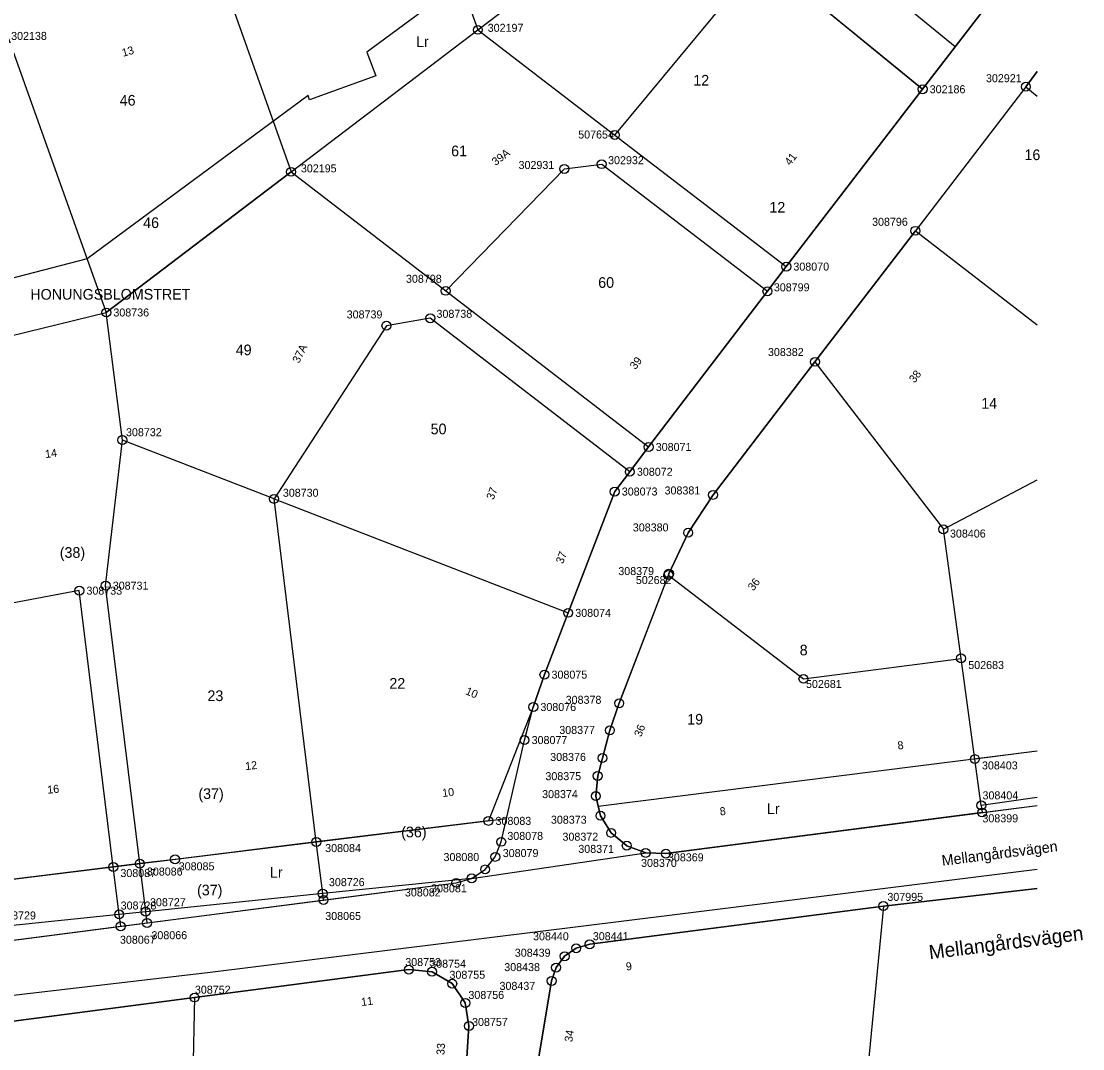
# Model space of a CAD drawing. Extents: x 141995 to 152570, y 6580184 to 6586000.
# Drawn here: x 142885.7 to 143005.1, y 6585147.6 to 6585263.2 of the extents above; entities that cross this region are included whole.
import ezdxf

# ---------------------------------------------------------------- set-up
doc = ezdxf.new("R2010")
doc.units = 0
for name, color, linetype in [('Level 10', 7, 'Continuous'), ('Level 34', 7, 'Continuous'), ('Level 42', 7, 'Continuous'), ('Level 43', 7, 'Continuous'), ('Level 48', 7, 'Continuous'), ('Level 5', 7, 'Continuous'), ('Level 50', 7, 'Continuous'), ('Level 51', 7, 'Continuous'), ('Level 52', 7, 'Continuous'), ('Level 53', 7, 'Continuous'), ('Level 54', 7, 'Continuous'), ('Level 55', 7, 'Continuous'), ('Level 59', 7, 'Continuous'), ('Level 6', 7, 'Continuous'), ('Level 60', 7, 'Continuous'), ('Level 7', 7, 'Continuous'), ('Level 9', 7, 'Continuous')]:
    doc.layers.add(name, color=color, linetype=linetype)

msp = doc.modelspace()

# ---------------------------------------------------------------- linework, layer by layer
at = {"layer": 'Level 10'}
for centre in [(142937.08, 6585262.24), (142987.1, 6585255.56), (142998.71, 6585255.85), (142952.49, 6585250.41), (142946.81, 6585246.6), (142951.01, 6585247.13), (142916.07, 6585246.27), (142986.29, 6585239.64), (142971.77, 6585235.61), (142933.47, 6585232.88), (142969.65, 6585232.83), (142895.29, 6585230.45), (142926.8, 6585228.96), (142931.73, 6585229.8), (142975, 6585224.9), (142897.1, 6585216.1), (142956.29, 6585215.32), (142954.17, 6585212.53), (142952.47, 6585210.3), (142963.53, 6585209.93), (142914.16, 6585209.48), (142989.44, 6585206.06), (142960.73, 6585205.68), (142958.51, 6585200.92), (142958.57, 6585201.07), (142892.26, 6585199.16), (142895.22, 6585199.72), (142947.24, 6585196.66), (142991.43, 6585191.54), (142944.57, 6585189.71), (142973.7, 6585189.24), (142943.32, 6585186.07), (142952.98, 6585186.49), (142951.93, 6585183.45), (142942.33, 6585182.35), (142951.1, 6585180.33), (142992.98, 6585180.21), (142950.56, 6585178.32), (142950.35, 6585176.05), (142993.7, 6585175), (142950.87, 6585173.84), (142993.8, 6585174.2), (142938.27, 6585173.26), (142952.07, 6585171.91), (142918.91, 6585170.89), (142939.71, 6585170.9), (142953.83, 6585170.47), (142939.04, 6585169.21), (142955.96, 6585169.66), (142958.23, 6585169.58), (142896.08, 6585168.08), (142899.06, 6585168.45), (142903.03, 6585168.93), (142937.9, 6585167.8), (142936.38, 6585166.79), (142934.64, 6585166.29), (142919.63, 6585165.08), (142919.72, 6585164.36), (142899.73, 6585163.04), (142982.69, 6585163.68), (142896.74, 6585162.74), (142896.91, 6585161.4), (142899.88, 6585161.78), (142948.14, 6585158.93), (142949.66, 6585159.38), (142946.84, 6585158.03), (142929.32, 6585156.53), (142931.93, 6585156.29), (142945.88, 6585156.76), (142934.2, 6585154.95), (142945.38, 6585155.26), (142905.22, 6585153.39), (142935.67, 6585152.78), (142936.08, 6585150.19)]:
    msp.add_circle(centre, 0.5, dxfattribs=at)
at = {"layer": 'Level 34'}
for points in [[(142868.26, 6585230.02), (142870.29, 6585224.35), (142895.29, 6585230.45), (142916.07, 6585246.27), (142937.08, 6585262.24), (142958.78, 6585278.74), (142987.1, 6585255.56), (142990.76, 6585260.32), (142959.77, 6585285.68), (142924.61, 6585259.72), (142925.59, 6585257.07), (142918.16, 6585254.37), (142918, 6585254.84), (142893.13, 6585236.49)], [(142788.7, 6585154.87), (142790.99, 6585151.54), (142793.5, 6585150.06), (142796.39, 6585149.74), (142819.3, 6585151.94), (142847.82, 6585155.05), (142934.64, 6585166.29), (142936.38, 6585166.79), (142937.9, 6585167.8), (142939.04, 6585169.21), (142939.71, 6585170.9), (142940.31, 6585173.51)]]:
    msp.add_lwpolyline(points, close=True, dxfattribs=at)
msp.add_lwpolyline([(143000, 6585181.09), (142950.62, 6585174.88), (142950.87, 6585173.84), (142952.07, 6585171.91), (142953.83, 6585170.47), (142955.96, 6585169.66), (142958.23, 6585169.58), (143000, 6585175.01)], dxfattribs=at)
at = {"layer": 'Level 5'}
for points in [[(143000, 6585272.35), (142987.1, 6585255.56)], [(142998.71, 6585255.85), (143000, 6585257.54)], [(142987.1, 6585255.56), (142971.77, 6585235.61)], [(142998.71, 6585255.85), (142986.29, 6585239.64)], [(142975, 6585224.9), (142986.29, 6585239.64)], [(142971.77, 6585235.61), (142969.65, 6585232.83)], [(142969.65, 6585232.83), (142956.29, 6585215.32)], [(142963.53, 6585209.93), (142975, 6585224.9)], [(142956.29, 6585215.32), (142954.17, 6585212.53)], [(142954.17, 6585212.53), (142952.47, 6585210.3)], [(142952.47, 6585210.3), (142947.24, 6585196.66)], [(142960.73, 6585205.68), (142963.53, 6585209.93)], [(142958.57, 6585201.07), (142960.73, 6585205.68)], [(142952.98, 6585186.49), (142958.51, 6585200.92)], [(142958.51, 6585200.92), (142958.57, 6585201.07)], [(142947.24, 6585196.66), (142944.57, 6585189.71)], [(142944.57, 6585189.71), (142943.32, 6585186.07)], [(142951.93, 6585183.45), (142952.98, 6585186.49)], [(142943.32, 6585186.07), (142938.27, 6585173.26)], [(142951.1, 6585180.33), (142951.93, 6585183.45)], [(142950.56, 6585178.32), (142951.1, 6585180.33)], [(143000, 6585181.09), (142992.98, 6585180.21)], [(142993.7, 6585175), (142992.98, 6585180.21)], [(142950.35, 6585176.05), (142950.56, 6585178.32)], [(142950.87, 6585173.84), (142950.35, 6585176.05)], [(142993.7, 6585175), (142993.8, 6585174.2)], [(142938.27, 6585173.26), (142918.91, 6585170.89)], [(142952.07, 6585171.91), (142950.87, 6585173.84)], [(142993.8, 6585174.2), (142958.23, 6585169.58)], [(142953.83, 6585170.47), (142952.07, 6585171.91)], [(142918.91, 6585170.89), (142903.03, 6585168.93)], [(142955.96, 6585169.66), (142953.83, 6585170.47)], [(142958.23, 6585169.58), (142955.96, 6585169.66)], [(142899.06, 6585168.45), (142896.08, 6585168.08)], [(142903.03, 6585168.93), (142899.06, 6585168.45)], [(142896.08, 6585168.08), (142877.39, 6585165.78)], [(142982.69, 6585163.68), (143000, 6585165.66)], [(142949.66, 6585159.38), (142982.69, 6585163.68)], [(142946.84, 6585158.03), (142948.14, 6585158.93)], [(142948.14, 6585158.93), (142949.66, 6585159.38)], [(142945.88, 6585156.76), (142946.84, 6585158.03)], [(142905.22, 6585153.39), (142929.32, 6585156.53)], [(142929.32, 6585156.53), (142931.93, 6585156.29)], [(142945.38, 6585155.26), (142945.88, 6585156.76)], [(142931.93, 6585156.29), (142934.2, 6585154.95)], [(142942.47, 6585137.91), (142945.38, 6585155.26)], [(142934.2, 6585154.95), (142935.67, 6585152.78)], [(142877.35, 6585149.77), (142905.22, 6585153.39)], [(142935.67, 6585152.78), (142936.08, 6585150.19)], [(142936.08, 6585150.19), (142934.45, 6585124.56)]]:
    msp.add_lwpolyline(points, dxfattribs=at)
at = {"layer": 'Level 6'}
for points in [[(142874.1, 6585158.44), (142896.91, 6585161.4), (142899.88, 6585161.78), (142919.72, 6585164.36), (142934.64, 6585166.29), (142936.38, 6585166.79), (142937.9, 6585167.8), (142939.04, 6585169.21), (142939.71, 6585170.9), (142942.33, 6585182.35), (142943.32, 6585186.07), (142944.57, 6585189.71), (142947.24, 6585196.66), (142952.47, 6585210.3), (142954.17, 6585212.53), (142956.29, 6585215.32), (142969.65, 6585232.83), (142971.77, 6585235.61), (142987.1, 6585255.56), (143000, 6585272.35)], [(143000, 6585257.54), (142998.71, 6585255.85), (142986.29, 6585239.64), (142975, 6585224.9), (142963.53, 6585209.93), (142960.73, 6585205.68), (142958.57, 6585201.07), (142952.98, 6585186.49), (142951.93, 6585183.45), (142951.1, 6585180.33), (142950.56, 6585178.32), (142950.35, 6585176.05), (142950.87, 6585173.84), (142952.07, 6585171.91), (142953.83, 6585170.47), (142955.96, 6585169.66), (142958.23, 6585169.58), (142993.8, 6585174.2), (143000, 6585175.01)], [(143000, 6585165.66), (142982.69, 6585163.68), (142949.66, 6585159.38), (142948.14, 6585158.93), (142946.84, 6585158.03), (142945.88, 6585156.76), (142945.38, 6585155.26), (142942.47, 6585137.91), (142941.82, 6585124.93), (142941.26, 6585112.77), (142941.13, 6585095.27), (142941.56, 6585088.17), (142942.17, 6585085.2), (142942.98, 6585081.21), (142945.35, 6585074.5), (142951.08, 6585061.25), (142953.19, 6585058.52), (142956.35, 6585057.13), (142959.79, 6585057.42), (142977.65, 6585063.6), (142986.19, 6585066.56), (142992.38, 6585069.18), (142998.18, 6585072.59), (143000, 6585074.01)], [(142934.45, 6585124.56), (142936.08, 6585150.19), (142935.67, 6585152.78), (142934.2, 6585154.95), (142931.93, 6585156.29), (142929.32, 6585156.53), (142905.22, 6585153.39), (142877.35, 6585149.77), (142873.36, 6585149.26), (142848.55, 6585146.03)]]:
    msp.add_lwpolyline(points, dxfattribs=at)
at = {"layer": 'Level 7'}
for points in [[(142906.73, 6585272.66), (142916.07, 6585246.27)], [(142952.49, 6585250.41), (142969.03, 6585270.35)], [(142987.1, 6585255.56), (142969.03, 6585270.35)], [(142934.48, 6585269.51), (142937.08, 6585262.24)], [(142884.19, 6585261.56), (142895.29, 6585230.45)], [(142916.07, 6585246.27), (142937.08, 6585262.24)], [(142937.08, 6585262.24), (142952.49, 6585250.41)], [(142998.71, 6585255.85), (143000, 6585254.78)], [(142952.49, 6585250.41), (142971.77, 6585235.61)], [(142946.81, 6585246.6), (142951.01, 6585247.13)], [(142951.01, 6585247.13), (142969.65, 6585232.83)], [(142916.07, 6585246.27), (142895.29, 6585230.45)], [(142916.07, 6585246.27), (142933.47, 6585232.88)], [(142946.81, 6585246.6), (142933.47, 6585232.88)], [(142986.29, 6585239.64), (143000, 6585229.06)], [(142933.47, 6585232.88), (142956.29, 6585215.32)], [(142870.29, 6585224.35), (142895.29, 6585230.45)], [(142897.1, 6585216.1), (142895.29, 6585230.45)], [(142931.73, 6585229.8), (142926.8, 6585228.96)], [(142954.17, 6585212.53), (142931.73, 6585229.8)], [(142926.8, 6585228.96), (142914.16, 6585209.48)], [(142975, 6585224.9), (142989.44, 6585206.06)], [(142895.22, 6585199.72), (142897.1, 6585216.1)], [(142914.16, 6585209.48), (142897.1, 6585216.1)], [(142989.44, 6585206.06), (143000, 6585211.62)], [(142918.91, 6585170.89), (142914.16, 6585209.48)], [(142914.16, 6585209.48), (142947.24, 6585196.66)], [(142991.43, 6585191.54), (142989.44, 6585206.06)], [(142958.51, 6585200.92), (142973.7, 6585189.24)], [(142899.06, 6585168.45), (142895.22, 6585199.72)], [(142892.26, 6585199.16), (142873.76, 6585195.7)], [(142896.08, 6585168.08), (142892.26, 6585199.16)], [(142973.7, 6585189.24), (142991.43, 6585191.54)], [(142992.98, 6585180.21), (142991.43, 6585191.54)], [(143000, 6585175.89), (142993.7, 6585175)], [(142936.38, 6585166.79), (142955.96, 6585169.66)], [(142959.25, 6585162.73), (143000, 6585167.82)], [(142936.38, 6585166.79), (142919.63, 6585165.08)], [(142919.63, 6585165.08), (142899.73, 6585163.04)], [(142982.69, 6585163.68), (142978.6, 6585121.48)], [(142896.74, 6585162.74), (142883.31, 6585161.36)], [(142899.73, 6585163.04), (142896.74, 6585162.74)], [(142906.68, 6585156.2), (142959.25, 6585162.73)], [(142863.92, 6585151.21), (142906.68, 6585156.2)], [(142905.22, 6585153.39), (142904.6, 6585125.07)]]:
    msp.add_lwpolyline(points, dxfattribs=at)
at = {"layer": 'Level 9'}
for points in [[(142919.63, 6585165.08), (142918.91, 6585170.89)], [(142899.73, 6585163.04), (142899.06, 6585168.45)], [(142896.74, 6585162.74), (142896.08, 6585168.08)], [(142919.72, 6585164.36), (142919.63, 6585165.08)], [(142896.91, 6585161.4), (142896.74, 6585162.74)], [(142899.88, 6585161.78), (142899.73, 6585163.04)]]:
    msp.add_lwpolyline(points, dxfattribs=at)

# ---------------------------------------------------------------- texts
at = {"layer": 'Level 42'}
msp.add_text('Mellangårdsvägen', height=1.2, rotation=7.2133, dxfattribs=at).set_placement((142989.33, 6585168.2))
at = {"layer": 'Level 43'}
msp.add_text('Mellangårdsvägen', height=1.6, rotation=7.2133, dxfattribs=at).set_placement((142987.91, 6585157.68))
at = {"layer": 'Level 48'}
for rotation, p in [(0.0493, (142930.13, 6585260.31)), (0.0493, (142969.6, 6585174.03)), (0.0514, (142913.7, 6585166.87))]:
    msp.add_text('Lr', height=1.2, rotation=rotation, dxfattribs=at).set_placement(p)
at = {"layer": 'Level 50'}
msp.add_text('HONUNGSBLOMSTRET', height=1.2, rotation=0.0493, dxfattribs=at).set_placement((142886.75, 6585231.89))
at = {"layer": 'Level 51'}
for s, p in [('12', (142961.31, 6585255.97)), ('46', (142896.8, 6585253.72)), ('61', (142934.08, 6585248.02)), ('60', (142950.62, 6585233.22)), ('49', (142909.85, 6585225.64)), ('14', (142993.7, 6585219.63)), ('50', (142931.77, 6585216.75)), ('8', (142973.28, 6585191.88)), ('22', (142927.13, 6585188.13)), ('23', (142906.67, 6585186.74)), ('19', (142960.63, 6585184.09))]:
    msp.add_text(s, height=1.2, rotation=0.0493, dxfattribs=at).set_placement(p)
at = {"layer": 'Level 52'}
for s, rotation, p in [('(38)', 0.0493, (142890.06, 6585202.85)), ('(37)', 0.0514, (142905.65, 6585175.72)), ('(36)', 0.0493, (142928.46, 6585171.41))]:
    msp.add_text(s, height=1.2, rotation=rotation, dxfattribs=at).set_placement(p)
at = {"layer": 'Level 53'}
for s, rotation, p in [('302197', 0.0493, (142938.19, 6585262.02)), ('302138', 0.0493, (142884.59, 6585261.11)), ('302921', 0.0493, (142994.23, 6585256.35)), ('302186', 0.0493, (142987.9, 6585255.11)), ('302195', 0.0493, (142917.18, 6585246.21)), ('302931', 0.0493, (142941.66, 6585246.59)), ('302932', 0.0493, (142951.73, 6585247.13)), ('308796', 0.0493, (142981.42, 6585240.2)), ('308070', 0.0493, (142972.57, 6585235.16)), ('308798', 0.0493, (142929, 6585233.79)), ('308799', 0.0493, (142970.37, 6585232.83)), ('308736', 0.0493, (142896.09, 6585230)), ('308739', 0.0493, (142922.33, 6585229.78)), ('308738', 0.0493, (142932.43, 6585229.85)), ('308382', 0.0493, (142969.71, 6585225.55)), ('308732', 0.0493, (142897.51, 6585216.53)), ('308071', 0.0493, (142957.09, 6585214.87)), ('308072', 0.0493, (142954.97, 6585212.08)), ('308730', 0.0493, (142915.15, 6585209.72)), ('308073', 0.0493, (142953.27, 6585209.86)), ('308381', 0.0493, (142958.08, 6585209.98)), ('308380', 0.0493, (142954.51, 6585205.82)), ('308406', 0.0493, (142990.18, 6585205.13)), ('308379', 0.0493, (142952.88, 6585200.91)), ('502682', 0.0493, (142954.85, 6585199.9)), ('308733', 0.0493, (142893.06, 6585198.71)), ('308731', 0.0493, (142896.02, 6585199.27)), ('308074', 0.0493, (142948.04, 6585196.21)), ('502683', 0.0493, (142992.24, 6585190.34)), ('308075', 0.0493, (142945.37, 6585189.26)), ('502681', 0.0493, (142973.99, 6585188.21)), ('308076', 0.0493, (142944.12, 6585185.62)), ('308378', 0.0493, (142946.96, 6585186.43)), ('308377', 0.0493, (142946.24, 6585183.04)), ('308077', 0.0493, (142943.13, 6585181.9)), ('308376', 0.0493, (142945.22, 6585180)), ('308403', 0.0493, (142993.78, 6585179.05)), ('308375', 0.0493, (142944.68, 6585177.84)), ('308374', 0.0493, (142944.31, 6585175.82)), ('308404', 0.0493, (142993.84, 6585175.68)), ('308083', 0.0493, (142939.07, 6585172.81)), ('308373', 0.0493, (142945.3, 6585172.94)), ('308399', 0.0493, (142993.83, 6585173.1)), ('308078', 0.0493, (142940.4, 6585171.12)), ('308372', 0.0493, (142946.6, 6585171.03)), ('308084', 0.0514, (142919.91, 6585169.75)), ('308080', 0.0493, (142933.22, 6585168.74)), ('308079', 0.0493, (142939.88, 6585169.19)), ('308371', 0.0493, (142948.38, 6585169.66)), ('308369', 0.0493, (142958.46, 6585168.71)), ('308085', 0.0514, (142903.44, 6585167.7)), ('308370', 0.0493, (142955.44, 6585168.08)), ('308087', 0.0514, (142896.88, 6585166.94)), ('308086', 0.0514, (142899.86, 6585167.11)), ('308726', 0.0514, (142920.33, 6585165.92)), ('308081', 0.0493, (142931.82, 6585165.22)), ('308082', 0.0493, (142928.88, 6585164.76)), ('307995', 0.0493, (142983.14, 6585164.26)), ('308728', 0.0514, (142896.91, 6585163.29)), ('308727', 0.0514, (142900.21, 6585163.66)), ('308729', 0.0514, (142883.36, 6585162.17)), ('308065', 0.0514, (142919.92, 6585162.11)), ('308067', 0.0514, (142896.83, 6585159.44)), ('308066', 0.0514, (142900.37, 6585159.95)), ('308440', 0.0493, (142943.29, 6585159.83)), ('308441', 0.0493, (142950.01, 6585159.84)), ('308439', 0.0493, (142941.24, 6585157.98)), ('308753', 0.0514, (142928.92, 6585156.93)), ('308754', 0.0514, (142931.73, 6585156.74)), ('308755', 0.0514, (142933.89, 6585155.5)), ('308438', 0.0493, (142940.05, 6585156.36)), ('308437', 0.0514, (142939.52, 6585154.25)), ('308752', 0.0514, (142905.26, 6585153.82)), ('308756', 0.0514, (142936.02, 6585153.23)), ('308757', 0.0514, (142936.43, 6585150.19))]:
    msp.add_text(s, height=0.9, rotation=rotation, dxfattribs=at).set_placement(p)
msp.add_text('507654', height=0.9, dxfattribs=at).set_placement((142948.37, 6585250.02))
at = {"layer": 'Level 54'}
for s, rotation, p in [('13', 15.9185, (142897.19, 6585259.21)), ('39A', 37.2936, (142939.08, 6585246.92)), ('41', 52.7666, (142972.21, 6585246.91)), ('37A', 63.4972, (142916.97, 6585224.67)), ('39', 52.6606, (142954.8, 6585223.96)), ('38', 52.5516, (142986.2, 6585222.46)), ('14', 7.3403, (142888.46, 6585214.07)), ('37', 69.0005, (142938.84, 6585209.31)), ('36', 52.3366, (142968.07, 6585199.07)), ('10', 336.5298, (142935.61, 6585187.54)), ('8', 7.3862, (142984.34, 6585181.28)), ('12', 5.8474, (142910.96, 6585178.97)), ('16', 5.8334, (142888.7, 6585176.31))]:
    msp.add_text(s, height=0.9, rotation=rotation, dxfattribs=at).set_placement(p)
at = {"layer": 'Level 55'}
for s, rotation, p in [('37', 69.0005, (142946.65, 6585202.1)), ('36', 68.7835, (142955.45, 6585182.64)), ('10', 6.9993, (142933.13, 6585175.94)), ('8', 7.0533, (142964.35, 6585173.87)), ('9', 7.4203, (142953.79, 6585156.42)), ('11', 7.4694, (142924.01, 6585152.43)), ('34', 81.629, (142947.7, 6585148.35)), ('33', 86.325, (142933.31, 6585146.9))]:
    msp.add_text(s, height=0.9, rotation=rotation, dxfattribs=at).set_placement(p)
at = {"layer": 'Level 59'}
for s, p in [('16', (142998.56, 6585247.59)), ('12', (142969.87, 6585241.68)), ('46', (142899.44, 6585239.95))]:
    msp.add_text(s, height=1.2, rotation=0.0493, dxfattribs=at).set_placement(p)
at = {"layer": 'Level 60'}
msp.add_text('(37)', height=1.2, rotation=0.0514, dxfattribs=at).set_placement((142905.5, 6585164.88))

doc.saveas('drawing.dxf')
